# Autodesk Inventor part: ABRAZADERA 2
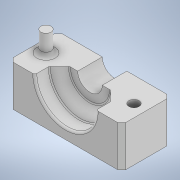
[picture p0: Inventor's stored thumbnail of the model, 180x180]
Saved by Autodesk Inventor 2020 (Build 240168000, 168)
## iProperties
Created: 2022-10
Part Number: ABRAZADERA 2
Material: Genérico
Document SubType Name: Modeling
Designer: SEBAS
Density: 1 g/cm^3
Appearance: Valor por defecto
Author: SEBAS
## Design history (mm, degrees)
sketch "Boceto1"
  geometry: L1 (0, 0)-(0, 24); L2 (0, 0)-(33, 0); L3 (33, 0)-(33, 12); L4 (33, 12)-(23, 12); L5 (23, 12)-(18, 17); L6 (18, 17)-(18, 24); L7 (18, 24)-(0, 24); L8 (33, 0)-(33, 24)
  constraints: 16 end point, 2 horizontal, 2 perpendicular, 2 vertical, 1 horizontal alignment, 1 parallel
  dimensions: "d0" = 24 distance of L1.start L1.end; "d1" = 12 distance of L2.end L3.end; "d2" = 7 distance of L5.end L6.end; "d3" = 18 distance of L6.end L1.end; "d4" = 33 distance between parallel lines of L1 L3; "d5" = 10 distance of L3.end L4.end
revolve "Revolución1" sketch "Boceto1" stored, may be unused: angle "d6" = 180 deg
sketch "Boceto2"
  geometry: L1 (0, 0)-(66, 0) reference; L2 (2, 0)-(64, 0); L3 (64, 0)-(64, 22); L4 (64, 22)-(2, 22); L5 (2, 22)-(2, 0); L6 (11.5, 12)-(54.5, 12); L7 (0, 24)-(66, 24) reference; L8 (0, 0)-(0, 24) reference; L9 (0, 24)-(66, 24); L10 (66, 24)-(66, 0); L11 (66, 0)-(0, 0); L12 (0, 0)-(0, 24); L13 (5.5, 0)-(60.5, 0); L14 (60.5, 0)-(60.5, 20); L15 (60.5, 20)-(5.5, 20); L16 (5.5, 20)-(5.5, 0); C1 r 2.5 at (11.5, 12); C2 r 2.5 at (54.5, 12); 10 further points
  constraints: 26 end point, 6 parallel, 5 midpoint, 4 horizontal, 3 perpendicular, 3 vertical alignment, 2 centre point, 2 point on line, 1 equal radius, 1 horizontal alignment
  dimensions: "d7" = 5 diameter of C1; "d8" = 43 distance of L6.start L6.end; "d9" = 12 distance from line of L7 L6.end; "d10" = 2 distance from line of L1.end L3; "d11" = 2 distance between parallel lines of L7 L4; "d20" = 55 distance of L14.end L15.end; "d21" = 20 distance of L13.end L14.end
extrude "Extrusión1" cut sketch "Boceto2" distance "d12" = 40; taper "d13" = 0 deg
sketch "Boceto3"
  geometry: L1 (46, 0)-(62, 0) reference; L2 (62, 0)-(0, 0); L3 (0, 0)-(0, -20); L4 (0, -20)-(62, -20); L5 (62, -20)-(62, 0); L6 (62, -20)-(0, -20); L7 (0, -20)-(0, -36); L8 (0, -36)-(62, -36); L9 (62, -36)-(62, -20); A1 r 33 centre (31, 0) between (0, -11.314) and (62, -11.314) reference; 5 further points
  constraints: 16 end point, 4 parallel, 2 horizontal, 2 perpendicular, 1 coincident, 1 vertical alignment
  dimensions: "d14" = 20 distance of L4.end L1.end; "d15" = 16 distance between parallel lines of L4 L8
extrude "Extrusión2" cut sketch "Boceto3" stored distance "d16" = 10; taper "d17" = 0 deg
extrude "Extrusión3" join sketch "Boceto3" stored distance "d18" = 10; taper "d19" = 0 deg
extrude "Extrusión4" cut sketch "Boceto2" stored distance "d22" = 10; taper "d23" = 0 deg
extrude "Extrusión5" join sketch "Boceto2" distance "d24" = 10; taper "d25" = 0 deg
extrude "Extrusión6" cut sketch "Boceto2" stored distance "d26" = 10; taper "d27" = 0 deg
fillet "Empalme1" dims "d28" = 2
fillet "Empalme2" dims "d29" = 1
sketch "Boceto5"
  geometry: L1 (0, 0)-(55, 0) reference; C1 r 6 at (27.5, 0); 1 further point
  constraints: 1 centre point, 1 midpoint
  dimensions: "d36" = 12 diameter of C1
extrude "Extrusión8" cut sketch "Boceto5" distance "d37" = 10; taper "d38" = 0 deg
sketch "Boceto6"
  geometry: L1 (0, 20)-(21.5, 20) reference; L2 (0, 20)-(0, 0) reference; L3 (55, 0)-(0, 0) reference; L4 (55, 20)-(55, 0) reference; L5 (33.5, 20)-(55, 20) reference; A1 r 6 centre (27.5, 20) between (21.5, 20) and (33.5, 20) reference; 1 further point
extrude "Extrusión9" join sketch "Boceto6" distance "d39" = 4; taper "d40" = 0 deg
chamfer "Chaflán2" distance "d41" = 2; stored, may be unused: second distance "d42" = 2, angle "d43" = 45 deg
node "Sólido1"
node "Contorno proyectado1"
